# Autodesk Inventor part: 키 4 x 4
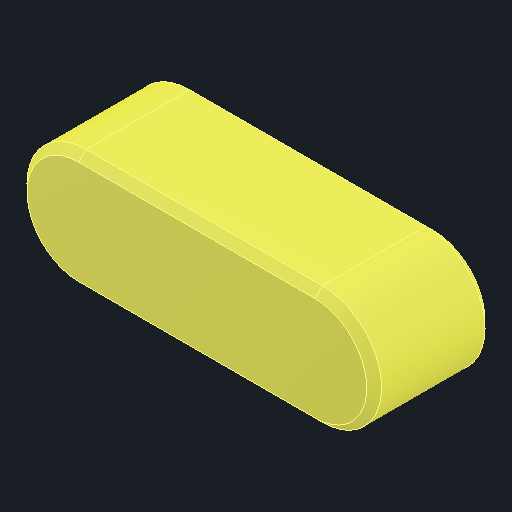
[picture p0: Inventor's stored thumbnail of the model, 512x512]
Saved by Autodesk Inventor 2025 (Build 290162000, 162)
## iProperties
Created: 2025-08
Part Number: 키 4 x 4
Material: 강철, 연강
Description: 키 및 해당 키홈
Document SubType Name: Modeling
Designer: infra14
Density: 7.86 g/cm^3
Appearance: 기본값
Author: jhkim
Sending System: Autodesk Inventor 2026
Preprocessor: ST-DEVELOPER v20.1
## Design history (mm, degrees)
feature "Solid1"
node "솔리드1"
